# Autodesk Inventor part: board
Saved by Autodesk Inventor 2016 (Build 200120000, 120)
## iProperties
Created: 2016-09
Part Number: board
Material: Generic
Document SubType Name: Modeling
Designer: Administrator
Appearance: Generic
Author: Administrator
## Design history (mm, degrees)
feature "Body3"
body "Solid1"
